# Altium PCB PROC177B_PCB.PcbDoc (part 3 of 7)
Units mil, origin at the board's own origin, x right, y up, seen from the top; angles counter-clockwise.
Board outline 4257.98 x 1561.15 mil, 4 copper layers (Top Layer, Int1 (GND), Int2 (PWR), Bottom Layer), stack 63.572 mil thick; 461 components, 307 nets, 1564 pads, 607 vias.
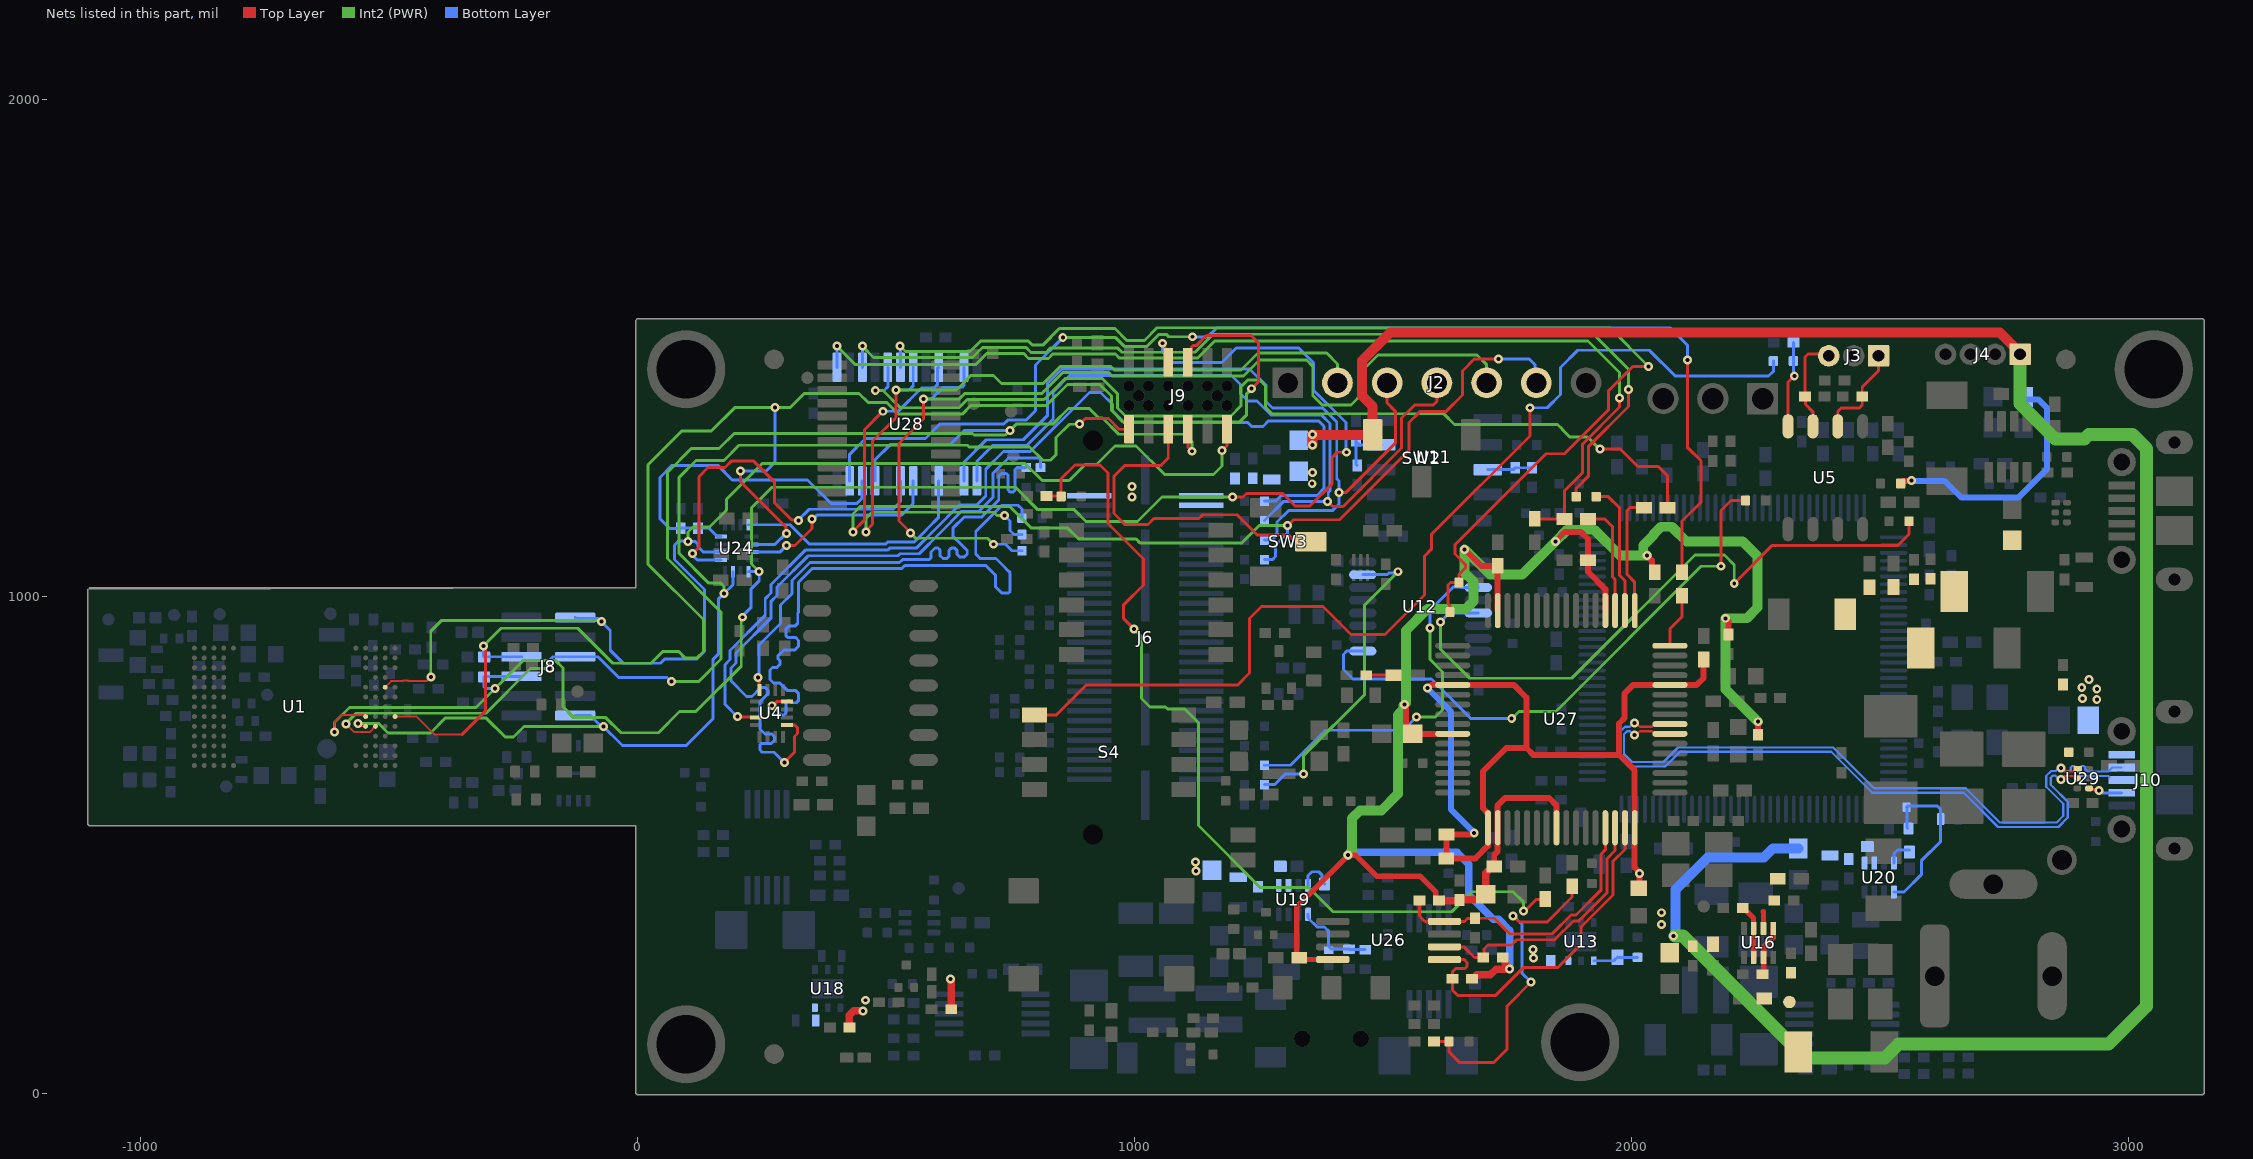
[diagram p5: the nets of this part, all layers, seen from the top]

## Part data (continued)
S3: library part CMP-0002325-1, "Switch, SPST-NO, Off-Mom, 0.01 A, 32 VDC, SMD", CurrentRating_mA=10A, Manufacturer="C&K Components", Supplier Part Number 1=401-1432-2-ND
S4: library part CMP-0002128-3, "Switch, Slide, SPST 4 poles, SMT", CurrentRating_mA=25A, Manufacturer="CTS Electrocomponents", Supplier Part Number 1=CT2184LPST-ND
S5: library part CMP-0002230-1, "Switch, SPST, 2 Pos, 25mA, 24VDC, SMD", CurrentRating_mA=25A, Manufacturer="CTS Electrocomponents", Supplier Part Number 1=CT2182LPST-ND
SW1: library part CMP-0096333-1, "Slide Switch SPDT Surface Mount, Right Angle", Coil Resistance_ohm=80mΩ, Contact Current Rating=100mA, Digikey Part Number=401-2012-1-ND, Manufacturer="C&K Switches", Mouser Part Number=611-AYZ0102AGRLC, Operating Temperature Range="-10°C to +60°C"
SW2: library part CMP-0120644-1, "C & K COMPONENTS - - Schiebeschalter, Subminiatur, SPDT, Ein-Ein, Oberflächenmontage, JS Series, 300 mA", Coil Resistance_ohm=70mΩ, Contact Current Rating=0.3A, Digikey Part Number=CKN10721CT-ND, Manufacturer="C&K Components", Mouser Part Number=611-JS102011JCQN, Operating Temperature Range="-40°C to +85°C"
SW3: library part CMP-0120641-1, "Slide Switch SPDT Surface Mount", Coil Resistance_ohm=100mΩ, Contact Current Rating=100mA, Digikey Part Number=CJS-1200A1-ND, Manufacturer="Nidec Components Corporation", Mouser Part Number=229-CJS-1200A1, Operating Temperature Range="-40°C to +85°C"
TP1 TP2 TP3 TP4 TP5 TP6 TP7 TP8 TP9 TP11 TP12 TP13 TP14 TP15 TP16: library part CMP-0078143-3, "TEST POINT.  No entry in BOM.", Manufacturer=N/A
TP10: library part CMP-0003825-1, "1mm Test Point, SMT", Manufacturer=Any
U1: library part CMP-0120794-2, Manufacturer="Texas Instruments", Operating Temperature Range=to
U2: library part CMP-0078466-1, "ULTRA LOW POWER, 16M-BIT [x 1/x 2/x 4] CMOS MXSMIO (SERIAL MULTI I/O) FLASH MEMORY, SON-8", Manufacturer="Macronix International Co., LTD", Supplier Part Number 1=1092-1178-1-ND
U3: library part CMP-0067398-2, "Automotive Grade, 1.4V-Capable +/-0.5degC Temperature Sensor with Alert Function and I2C/SMBus, DRL0006A (SOT-OTHER-6)", Alternate Manufacturer="Texas Instruments"
U4 U24: library part CMP-0067415-1, "10-Ohm Quad SPDT Analog Switch, RSV0016A (UQFN-16)", Alternate Manufacturer="Texas Instruments"
U5: library part CMP-0075992-1, "Automotive Fault Protected CAN Transceiver With Flexible Data-Rate, D0008A (SOIC-8)", Alternate Manufacturer="Texas Instruments", Alternate PartNumber=TCAN1042HGVDRQ1
U6 U7 U8 U25: library part CMP-0098432-1, "Current Sense Amplifier 1 Circuit 10-VSSOP", Digikey Part Number=296-INA228AIDGSTCT-ND, Input Bias Current=0.01uA, Input Offset Voltage=1mV, Manufacturer="Texas Instruments", Max Supply Voltage=5.5V, Min Supply Voltage=2.7V, Mouser Part Number=595-INA228AIDGST, Nominal Supply Current=640uA, Operating Temperature Range="-40°C to +125°C"
U9 U29: library part CMP-0043115-3, "4-Channel ESD Protection Array for High-Speed Data Interfaces, DRY0006A (USON-6)", Breakdown Voltage(Min)(V)=6, IO Capacitance(Typ)(pF)=1.6, IO Leakage Current(nA)=1, Manufacturer="Texas Instruments", Operating Temperature Range="-40 to 85 C", Rating=Catalog
U10 U14: library part CMP-0029468-1, "400 Mbps Enhanced Product Quad LVDS Transmitter with LVTTL Input and Output, 4 Tx and 0 Rx, -55 to +125 degC, 16-pin SOIC (D), Green (RoHS & no Sb/Br)", Manufacturer="Texas Instruments"
U11: library part CMP-0005309-2, "IC, EEPROM, 8KBIT, 400KHZ, 8SOIC", Manufacturer="ON Semiconductor", Supplier Part Number 1=CAT24C08WI-GT3CT-ND
U12: library part CMP-0067412-1, "0.45-Ohm Quad SPDT Analog Switch Quad-Channel 2:1 Multiplexer/Demultiplexer with Two Controls, PW0016A (TSSOP-16)", Alternate Manufacturer="Texas Instruments"
U13 U18: library part CMP-0013427-7, "500mA LDO, DRV0006A (WSON-6)", Alternate Manufacturer="Texas Instruments"
U15 U28: library part CMP-0092155-1, "3.3-V, 2:1 (SPDT), 6-channel analog multiplexer with 1.8-V compatible control inputs 24-TSSOP -40 to 85", Digikey Part Number=296-24570-1-ND, Manufacturer="Texas Instruments", Max Supply Voltage=3.6V, Min Supply Voltage=1.65V, Mouser Part Number=595-TS3A27518EPWR, Nominal Supply Current=0.01-0.04uA, Octopart Part Number=cf0206a9c1b910c5, On State Resistance=4.4Ω, Operating Temperature Range="-40°C to +85°C"
U16: library part CMP-0088593-2, "1.6 V to 5 V, 2.5-A Low IQ Power Mux With Manual and Automatic Switchover", Manufacturer="Texas Instruments", Max Supply Voltage=5.5V, Min Supply Voltage=1.6V, Nominal Supply Current=0.5-1uA, Operating Temperature Range=to, Output Voltage=0-5.5V
U17: library part CMP-0051215-4, "Single 3-Input Positive-AND Gate, DSF0006A, LARGE T&R", F @ Nom Voltage(Max)(Mhz)=150, Generic Part Number=SN74LVC1G11, ICC @ Nom Voltage(Max)(mA)=0.01, Manufacturer="Texas Instruments", Operating Temperature Range(C)="-40 to 125,-40 to 85", Rating=Catalog, tpd @ Nom Voltage(Max)(ns)=20,7.8,6.2,4.6, Voltage(Nom)(V)=1.8,2.5,3.3,5
U19: library part CMP-0120067-1, "2.7-V to 6-V, 2-A Step-Down Converter in SOT583 Package", Manufacturer="Texas Instruments", Max Supply Voltage=6V, Min Supply Voltage=2.7V, Nominal Supply Current=17uA, Operating Temperature Range="-40°C to +150°C", Output Voltage=0.6-5.5V, Switching Frequency=1.8-4MHz
U20: library part CMP-0120069-1, "2.7-V to 6-V, 2-A Step-Down Converter in SOT583 Package", Manufacturer="Texas Instruments", Max Supply Voltage=6V, Min Supply Voltage=2.7V, Nominal Supply Current=17uA, Operating Temperature Range="-40°C to +150°C", Output Voltage=0.6-5.5V, Switching Frequency=1.8-4MHz
U21: library part CMP-0029856-2, "Tiva C Series Microcontroller, 1024 KB Flash, 256 KB SRAM, 12 Bit, 20 Channels, -40 to 105 degC, 128-Pin TQFP (PDT), Green (RoHS & no Sb/Br), Tray", Manufacturer="Texas Instruments", Temperature Range="-40 to 105 degC"
U22: library part CMP-0033001-1, "Precision Micropower Shunt Voltage Reference, 0.5% accuracy, 2.5 V, 15 ppm / degC, 15 mA, -40 to 125 degC, 3-pin SOT-23 (DBZ), Green (RoHS & no Sb/Br)", Manufacturer="Texas Instruments", Rating=Catalog, Temp Coeff(Max)(ppm/ degree C)=100, Temp Coeff(Typ)(ppm/ degree C)=15
U23: library part CMP-0090433-1, "Local Interconnect Network (LIN) Transceiver with Dominant State Timeout", Manufacturer="Texas Instruments", Max Supply Voltage=36V, Min Supply Voltage=4.5V, Nominal Supply Current=0.3-1.2mA, Operating Temperature Range="-40°C to +150°C"
U26: library part CMP-0081524-1, "1K Microwire Compatible Serial EEPROM, TSSOP-8", Manufacturer=Microchip, Supplier Part Number 1=93LC46B-I/ST-ND
U27: library part CMP-0004747-1, "Quad High Speed USB to Multipurpose UART/MPSSE IC", Manufacturer=FTDI, Supplier Part Number 1=768-1026-1-ND
Y1: library part CMP-0120019-1, "Crystal Resonator 40MHz ±10ppm (Tol) ±20ppm (Stability) 8pF 50Ohm 4-Pin SMD T/R", Frequency Stability=20ppm, Frequency Tolerance=10ppm, Frequency_Fixed=40MHz, Load Capacitance=8pF, Manufacturer=Murata, Operating Temperature Range="-40°C to +105°C"
Y2: library part CMP-0095014-1, "16 MHz ±15ppm Crystal 8pF 80 Ohms 4-SMD, No Lead", Digikey Part Number=50-ECS-160-8-33Q-RES-CT-ND, Frequency_Fixed=16MHz, Frequency Stability=50ppm, Frequency Tolerance=15ppm, Load Capacitance=8pF, Manufacturer=ECS, Mouser Part Number=520-ECS160833QRES-TR, Operating Temperature Range="-40°C to +125°C"
Y3: library part CMP-0081529-1, "Crystal, 12 MHz, 15 ppm, 8 pF, AEC-Q200 Grade 1, SMD", Frequency Stability="50 ppm", Frequency Tolerance="15 ppm", Frequency_Fixed=12MHz, Load Capacitance="8 pF", Manufacturer=NDK, Supplier Part Number 1=644-1128-1-ND
ZZ1: library part CMP-0003616-3
ZZ2: library part CMP-0077236-1
ZZ3: library part CMP-0077237-1
ZZ4 ZZ5: library part CMP-0077238-1

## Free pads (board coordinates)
  round 157.48 hole 118.11: TH1(98.41,1456.71) TH2(1896.85,102.75) TH4(3051.18,1456.69) TH9(98.43,98.43)

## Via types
v1: diameter 18, hole 8, Top Layer to Bottom Layer, tented both sides, 603 vias
v2: diameter 19.68, hole 7.87, Top Layer to Bottom Layer, 4 vias

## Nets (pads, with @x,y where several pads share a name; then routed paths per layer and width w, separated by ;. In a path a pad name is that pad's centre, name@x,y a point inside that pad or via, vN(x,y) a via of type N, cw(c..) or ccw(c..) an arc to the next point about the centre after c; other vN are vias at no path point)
1V2_FB: C100.2 R119.1 R121.2 U19.5 | length 166.4
  Bottom Layer w5.9: U19.5@1349.73,360.08 1349.73,352.79 1368.04,334.48 1382.68,334.48 1391.2,325.97 1391.2,295.69 1397.02,289.86 R119.1@1432.18,289.86 1432.68,289.36 1464.11,289.36 R121.2@1464.61,288.86
1V8_FB: C1.2 R35.2 R36.2 U20.5 | length 333.5
  Bottom Layer w5.9: U20.5@2528.12,404.76 2548.33,404.76 2583.36,439.79 2583.36,467.62 2622.28,506.54 R36.2@2622.28,551.6 2622.28,571.19 2615.58,577.89 2556.03,577.89 C1.2@2553.75,575.6 2554.73,574.62 2554.73,533.43 R35.2@2555.71,532.44
3V3_LDO_EN: R11.2 R241.2 U13.4 | length 91.2
  Bottom Layer w5.9: U13.4@1924.39,266.53 1964.49,266.53 R11.2@1971.93,273.97 1972.44,273.45 R241.2@2012.34,273.45
5V_IN: C42.1 C51.1 C62.1 C66.1 C67.1 C69.2 C72.1 C73.1 C74.1 C134.1 C135.1 J4.1 R30.1 R31.1 R69.2 R76.2 R141.2 R174.2 R238.1 R244.1 SW2.3 U13.6 U16.2 U16.7 U18.6 U19.1 U19.2 U20.1 U20.2 | length 5400.5
  Top Layer w11: R76.2@2224.29,372.62 2226.26,372.62 2230.61,368.27 2230.61,367.69 2245.75,352.54 2245.75,332.14 U16.7@2246.16,331.74 2245.75,331.33 2245.75,305.06 2242.48,301.8 2246.16,298.12 U16.2@2246.16,273.47
  Top Layer w12: R69.2@2541.66,1226.67 2541.66,1227.01 2546.01,1231.36 2562.48,1231.36 v1(2564.01,1232.89)
  Top Layer w15: R174.2@427.08,132.35 427.08,156.98 435.87,165.77 v1(454.21,165.77) ; v1(630,229.6) 630,228.79 631.69,227.1 R141.2@631.69,169
  Top Layer w20: v1(1358.35,1325.28) v1@1358.69,1324.94 ; v1(1358.69,1303.81) v1@1358.69,1324.94 ; J4.1@2782.04,1486.59 2770.39,1498.24 2770.39,1501.49 2741.79,1530.1 1514.28,1530.1 1458.54,1474.35 1458.54,1402.93 1479.68,1381.78 SW2.3@1479.68,1324.48 1359.16,1324.48 v1@1358.69,1324.94
  Int2 (PWR) w26: v1@2088.18,316.08 2104.18,316.08 2348.93,71.33 2510.13,71.33 2537.73,98.93 2960.23,98.93 3036,174.7 3036,1297.46 3008.46,1325 2920.14,1325 2911.5,1316.36 2853.03,1316.36 2782.04,1387.35 J4.1@2782.04,1486.59
  Bottom Layer w12: v1(2564.01,1232.89) 2564.79,1232.11 2630.08,1232.11 2664.07,1198.12 2778.43,1198.12 2836,1255.7 2836,1378.79 2818.74,1396.05 2793.71,1396.05 R31.1@2789.07,1400.7
  Bottom Layer w20: v1(2084.62,316.08) 2088.75,320.22 2088.75,409.49 2153.63,474.37 2266.46,474.37 2284.58,492.48 C72.1@2335.86,492.48
  other v1: 459.51,187.12 1802.86,271.75 1802,289.6 2060.38,339.86 2060.98,363.18 1123.96,447.52 1123.13,465.5
5V_IN_USB: C46.2 C47.1 C50.2 C55.1 C84.1 C85.2 C137.1 D1.1 D12.1 R1.2 U16.6 | length 33.7
  Top Layer w11: 2265.49,365.33 2265.84,364.98 U16.6@2265.84,331.74
5V_REG: C49.1 C136.1 D2.1 R102.2 TP12.1 U16.3 U16.5 | length 101.1
  Top Layer w11: C136.1@2263.68,239.6 2266.01,241.93 U16.3@2266.01,273.3 ; U16.3@2265.84,273.47 2266.25,273.87 2266.25,293.84 2285.19,312.78 2285.19,331.4 U16.5@2285.53,331.74
CAN_PHY_RX: R80.1 U12.5 | length 1320.2
  Top Layer w5.9: v1(2207,1025.6) 2283.67,1102.27 2536.24,1102.27 2558.76,1124.79 R80.1@2558.76,1150.59
  Int2 (PWR) w5.9: v1(1615.79,948.25) 1615.79,893.97 1674.87,834.89 1880.28,834.89 2128,1082.6 2187.17,1082.6 2207,1062.78 v1(2207,1025.6)
  Bottom Layer w5.9: v1(1615.79,948.25) 1633.82,966.28 U12.5@1691.95,966.28
CAN_PHY_TX: R78.1 U12.9 | length 1169.2
  Top Layer w5.9: v1(2180.26,1060.19) 2180.26,1172.34 2200.43,1192.52 R78.1@2229.76,1192.52
  Int2 (PWR) w5.9: v1(1759.37,753.6) 1774.01,768.24 1848.35,768.24 2140.3,1060.19 v1(2180.26,1060.19)
  Bottom Layer w5.9: U12.9@1459.67,889.51 1427.54,889.51 1420.77,882.73 1420.77,852.77 1440.32,833.21 1598.07,833.21 1677.68,753.6 v1(1759.37,753.6)
CAN_STB: R3.2 R71.2 U5.8 | length 174.8
  Top Layer w5.9: U5.8@2315.27,1341.57 2315.27,1430.38 2327.74,1442.84 v1(2327.74,1443.37)
  Bottom Layer w5.9: R71.2@2325.96,1510.51 2325.96,1472.96 2325.96,1445.15 v1(2327.74,1443.37)
CAN_STB_CTRL: R3.1 S4.1 | length 2075.5
  Top Layer w5.9: S4.1@799.68,761.36 843.47,761.36 903.81,821.71 1208.52,821.71 1232,845.19 1232,907.65 1231.96,907.68 1231.96,943.81 1232,943.85 1232,955.29 1256.19,979.48 1379.83,979.48 1436.17,923.15 1504.64,923.15 1583.63,1002.13 1583.63,1080.33 1597.59,1094.28 1597.59,1123.94 1796.09,1322.45 v1(1796.09,1379.06)
  Bottom Layer w5.9: v1(1796.09,1379.06) 1830.83,1379.06 1857.58,1405.81 1857.58,1460.29 1892.04,1494.75 2036.18,1494.75 2088.26,1442.67 2276.17,1442.67 2285.61,1452.11 R3.1@2285.61,1472.96
CANH: J3.3 R68.2 U5.7 | length 198.1
  Top Layer w5.9: U5.7@2365.27,1341.57 2365.06,1341.79 2365.06,1371.18 2350.11,1386.13 2350.11,1400.45 R68.2@2349.1,1401.45 2349.1,1480.88 2355.27,1487.05 2393.75,1487.05 J3.3@2397.23,1483.56
CANL: J3.1 R79.1 U5.6 | length 197.2
  Top Layer w5.9: U5.6@2415.27,1341.57 2415.27,1371.53 2421.9,1378.16 2458.13,1378.16 2464.56,1384.59 R79.1@2464.56,1401.45 2464.56,1420.96 2497.23,1453.63 J3.1@2497.23,1483.56
COMP2: R178.2 U19.4 | length 73.6
  Bottom Layer w5.9: U19.4@1349.73,418.35 1349.73,438.04 1357.37,445.68 1370.99,445.68 1377.28,439.39 1377.28,427.1 R178.2@1383.11,421.26
COMP3: R180.2 U20.4 | length 53.2
  Bottom Layer w5.9: U20.4@2528.12,463.02 2528.12,481.76 2535.64,489.29 R180.2@2559.5,489.29
CONN_5V: C92.1 C93.1 C96.2 J6.1 J6.2 J6.3 R30.2
  other v1: 995.35,1199.21 995.04,1220.86 1358.05,1226.22 1359.02,1249.06
CONN_SOP0_TDO: J9.5 SW3.2 | length 693.2
  Top Layer w5.9: J9.5@1068.36,1335.77 1068.36,1278.08 1053.29,1263 980.67,1263 959.15,1241.48 959.15,1166.05 980.88,1144.32 1027.74,1144.32 1039.42,1156 1130.12,1156 1137.93,1163.8 1206.89,1163.8 1247.91,1122.78 1310.83,1122.78 1318.3,1115.31 1349.14,1115.31 SW3.2@1355.19,1109.26
DCA_FTDI_HOST_INTR_1: R23.2 R152.1 U24.12 U28.10 | length 708.7
  Bottom Layer w5.9: U24.12@168.91,1120.04 161.03,1120.04 144.32,1136.76 R23.2@122.49,1136.76 88.17,1136.76 R152.1@87.87,1136.46 65.14,1136.46 46,1155.6 46,1238.95 70.25,1263.2 162.21,1263.2 191.48,1233.93 342.87,1233.93 389.97,1186.82 442,1186.82 452.27,1197.1 452.27,1231.21 U28.10@453.08,1232.02
DCA_FTDI_SPI_CLK: U24.16 U28.4 | length 494.3
  Bottom Layer w5.9: U24.16@224.02,1143.67 307.63,1143.67 346.12,1105.18 500.11,1105.18 504.07,1109.14 557.48,1109.14 582.05,1133.71 582.05,1134.11 606.62,1158.68 U28.4@606.62,1232.02
DCA_FTDI_SPI_CS: U24.3 U28.6 | length 420.8
  Top Layer w5.9: v1(300.48,1101.72) 317.29,1101.72 351.95,1136.39 v1(351.95,1155.37)
  Bottom Layer w5.9: U24.3@231.9,1088.55 287.04,1088.55 300.22,1101.72 v1(300.48,1101.72) ; v1(351.95,1155.37) 353.81,1155.37 361.46,1163.02 531.99,1163.02 555.12,1186.15 555.12,1231.69 U28.6@555.44,1232.02
DCA_FTDI_SPI_MISO: U24.9 U28.7 | length 775.4
  Top Layer w5.9: v1(111.26,1085.51) 124.23,1098.49 124.23,1240.14 142.7,1258.6 176.73,1258.6 190.49,1272.36 233.53,1272.36 276.67,1229.23 276.67,1187.51 311.2,1152.98 323.7,1152.98 v1(324.17,1152.51)
  Bottom Layer w5.9: v1(111.26,1085.51) 111.26,1082.37 121.01,1072.62 168.72,1072.62 U24.9@168.91,1072.8 ; v1(324.17,1152.51) 324.17,1152.98 346.12,1174.92 514.2,1174.92 529.85,1190.57 U28.7@529.85,1232.02
DCA_FTDI_SPI_MOSI: J8.8 J9.7 U1.E3 U28.9 | length 2894.8
  Top Layer w4: v1(-586.13,743.28) -569.38,726.54 -538.16,726.54 U1.E3@-526.56,738.15
  Top Layer w5.9: J9.7@1107.73,1335.77 1107.73,1300.58 1115.93,1292.38 v1(1115.93,1291.54)
  Int2 (PWR) w5.9: v1(-586.13,743.28) -564.88,764.53 -304.2,764.53 -214.46,854.27 v1(-177,854.27) ; v1(69.31,827.96) 123.16,827.96 168.88,873.69 168.88,967.69 60.76,1075.81 60.76,1249.04 108.67,1296.95 164.59,1296.95 195.13,1327.49 674.34,1327.49 677.7,1324.14 740.31,1324.14 v1@749.28,1333.11 ; v1(749.81,1333.11) 762.65,1345.95 836.15,1345.95 867.72,1377.52 909.49,1377.52 928.6,1358.41 936.08,1358.41 968.69,1325.8 1101.54,1325.8 1115.93,1311.41 v1(1115.93,1291.54)
  Bottom Layer w5.9: v1(-177,854.27) -177,870.35 -169.21,878.14 J8.8@-124.58,878.14 -78.58,878.14 -37.05,836.6 59.8,836.6 68.44,827.96 v1(69.31,827.96) ; U28.9@478.67,1232.02 478.67,1274.27 509.95,1305.55 630.31,1305.55 657.88,1333.11 v1(749.81,1333.11)
DCA_HOST_INTR_1: J2.2 R42.2 U28.19 | length 1747.9
  Top Layer w5.9: v1(460,1129.07) 460,1131.11 473.69,1144.8 473.69,1311.95 521.01,1359.28 v1(521.01,1415.01)
  Int2 (PWR) w5.9: v1(460,1129.07) 460,1156.52 472.32,1168.84 717.37,1168.84 723.67,1162.54 739.02,1162.54 v1(739.06,1162.5) ; v1(521.01,1415.01) 642.25,1415.01 670.96,1443.72 717.02,1443.72 733.09,1427.66 816.89,1427.66 851.13,1461.9 953.44,1461.9 960.34,1455.01 1214.94,1455.01 1249.15,1489.22 1387.14,1489.22 1409.04,1467.33 J2.2@1409.04,1429
  Bottom Layer w5.9: v1(521.01,1415.01) 547.02,1415.01 555.44,1423.43 U28.19@555.44,1460.36 ; v1(739.06,1162.5) 750.24,1151.32 750.24,1131.92 758.23,1123.93 R42.2@774.11,1123.93
DCA_HOST_INTR_GPIO_0_LED: J8.12 J9.11 U1.J2 U24.10 | length 2539.8
  Top Layer w4: U1.J2@-506.87,816.89 -494.86,828.9 -471.78,828.9 -470.67,830.01 -461.28,830.01 -460.28,829.01 -423.78,829.01 -415.51,837.27 v1(-415.12,837.27)
  Top Layer w5.9: v1(1176.44,1292.66) 1176.44,1292.81 1186.47,1302.84 J9.11@1186.47,1335.77
  Int2 (PWR) w5.9: v1(-415.12,837.27) -415.22,837.38 -415.22,929.49 -393.25,951.46 -81.19,951.46 -80.7,950.97 -74,950.97 v1(-71.68,948.66) ; v1(102.51,1110.43) 102.51,1129.32 112.21,1139.02 145.67,1139.02 179.58,1172.94 179.58,1194.87 251.7,1266.99 780.43,1266.99 814.97,1232.44 869.07,1232.44 901.28,1264.65 923.98,1264.65 961.33,1302 1003.79,1302 1061.23,1244.55 1159.24,1244.55 1176.44,1261.75 v1(1176.44,1292.66)
  Bottom Layer w5.9: J8.12@-124.58,956.88 -122.56,954.85 -79.28,954.85 -73.09,948.66 v1(-71.68,948.66) -54.12,931.1 -54.12,891.33 -27.91,865.12 46.89,865.12 55.29,873.53 119.83,873.53 135.27,888.97 135.27,1013.64 75.39,1073.53 75.39,1102.36 83.72,1110.69 v1@102.25,1110.69 ; v1(102.51,1110.43) 116.54,1110.43 122.51,1104.47 122.51,1099.65 133.61,1088.55 U24.10@168.91,1088.55
DCA_RS232_RX: R61.1 U12.3 | length 732.2
  Int2 (PWR) w5.9: v1(1567.97,756.74) 1606.25,756.74 1620.26,770.75 1620.26,847.75 1595.24,872.77 v1(1595.24,935.84)
  Bottom Layer w5.9: R61.1@1262.19,659.92 1314.3,659.92 1384.61,730.23 1541.46,730.23 v1(1567.97,756.74) ; v1(1595.24,935.84) 1595.24,972.22 1641.59,1018.57 1656.74,1018.57 1657.85,1017.46 U12.3@1691.95,1017.46
DCA_RS232_TX: R62.1 U12.15 | length 646.3
  Int2 (PWR) w5.9: v1(1340.89,642.19) 1340.89,679.79 1463.53,802.42 1463.53,982.29 v1(1530.41,1049.17)
  Bottom Layer w5.9: R62.1@1262.19,620.73 1282.16,620.73 1303.62,642.19 v1(1340.89,642.19) ; U12.15@1459.67,1043.05 1460.33,1043.71 1509.26,1043.71 1512.56,1047.01 1528.25,1047.01 v1(1530.41,1049.17)
DCA_SPI_CLK: J2.3 R41.1 U28.2 | length 1611.5
  Top Layer w5.9: v1(1411.67,1208.61) 1412.12,1208.16 1425.56,1208.16 1525.21,1307.81 1525.21,1372.04 1508.83,1388.42 J2.3@1508.83,1429.21
  Bottom Layer w5.9: U28.2@657.8,1232.02 657.8,1269.97 702.48,1314.65 776.9,1314.65 825.1,1362.84 825.1,1428.05 854.21,1457.16 1232.02,1457.16 1264.81,1424.37 1264.81,1391.81 1278.03,1378.6 1379.21,1378.6 1407.37,1350.44 1407.37,1236.25 1411.67,1231.95 v1(1411.67,1208.61) 1411.67,1185.14 1398.49,1171.96 1310.23,1171.96 1287.29,1149.02 1287.29,1123.06 1276.94,1112.7 R41.1@1262.19,1112.68
DCA_SPI_CLK_I2C_SCL: J8.7 J9.8 R75.1 U1.F1 U24.2 | length 3501.1
  Top Layer w4: U1.F1@-487.19,757.83 -443.74,757.83 -407.96,722.05 -351.88,722.05
  Top Layer w5.9: -351.88,722.05 -305.4,768.53 -305.4,893.16 -309.12,896.88 v1(-309.12,899.58) ; v1(208.26,1251.88) 208.26,1229.96 299.55,1138.67 299.55,1126.2 v1(300.04,1125.72) ; J9.8@1107.73,1470.81 1114.62,1477.7 1114.62,1500.5 1118.08,1503.96 1124.91,1503.96 1145.25,1524.3 1235.22,1524.3 1249.58,1509.93 1249.58,1431.1 1236.3,1417.82 v1(1236.3,1417.33)
  Int2 (PWR) w5.9: v1(-309.12,899.58) -309.12,900.35 -273.97,935.49 -119.34,935.49 -48.97,865.12 27.95,865.12 51.95,889.12 83.14,889.12 96.97,875.28 119.99,875.28 133.18,888.47 133.18,952.84 21.86,1064.16 21.86,1264.32 90.19,1332.65 149.8,1332.65 196.36,1379.2 v1(277,1379.2) 307.25,1379.2 336.05,1408 446.29,1408 464.37,1389.92 501.67,1389.92 525.52,1366.08 653.79,1366.08 671.74,1384.02 823.74,1384.02 865.69,1425.98 930.72,1425.98 954.26,1402.44 954.26,1373.89 978.09,1350.06 1211.38,1350.06 1226.23,1364.92 1226.23,1407.23 v1@1236.3,1417.3
  Bottom Layer w5.9: v1(-309.12,899.58) -309.12,879.22 R75.1@-307.64,877.74 -307.24,878.14 J8.7@-232.85,878.14 ; v1(208.26,1251.88) 259.49,1251.88 277,1269.38 v1(277,1379.2) ; U24.2@231.9,1104.3 277.48,1104.3 298.9,1125.72 v1(300.04,1125.72)
DCA_SPI_CS: J2.4 R39.1 U28.1 | length 1589.8
  Top Layer w5.9: v1(1388.89,1190.89) 1399.36,1180.41 1420.36,1180.41 1537.79,1297.84 1537.79,1358.17 1564.63,1385 1601.72,1385 1609,1392.28 1609,1429.04 J2.4@1608.83,1429.21
  Bottom Layer w5.9: U28.1@683.39,1232.02 683.39,1271.54 714.58,1302.73 783.42,1302.73 837,1356.31 837,1411.07 869.71,1443.78 1195.8,1443.78 1213.94,1425.65 1213.94,1407.41 1228.58,1392.77 1247.03,1392.77 1274.99,1364.8 1376.17,1364.8 1393.52,1347.46 1393.52,1212.01 1390.25,1208.74 1390.25,1192.25 v1(1388.89,1190.89) 1300.71,1190.89 1262.19,1152.37 R39.1@1262.19,1151.87
DCA_SPI_CS_I2C_SDA: J8.5 J9.6 R4.1 U1.F4 U24.5 | length 3575.3
  Top Layer w4: v1(-608.65,726.98) -608.65,746.94 -594.59,760.99 -549.4,760.99 U1.F4@-546.24,757.83
  Top Layer w5.9: v1(1057.01,1508.83) 1057.01,1505.56 1061.47,1501.1 1061.47,1477.7 J9.6@1068.36,1470.81 ; v1(1197.32,1199.53) 1218.96,1199.53 1225.77,1206.33 1298.75,1206.33 1323.74,1181.34 1353.12,1181.34 1398.15,1226.38 1398.15,1279.15 1408.53,1289.53 v1(1426.53,1289.53)
  Int2 (PWR) w5.9: v1(-608.65,726.98) -608.65,746.22 -578.78,776.08 -323.93,776.08 -229.8,870.22 -163.91,870.22 -149.23,855.54 -149.23,819.89 -149.23,777.53 -127.35,755.64 -63,755.64 -32.59,725.23 42.83,725.23 85.41,767.82 118.01,767.82 209.38,859.18 209.38,955.42 v1(211.58,957.63) ; v1(245.55,1049.24) 229.85,1064.93 229.85,1177.82 271.13,1219.1 760.99,1219.1 806.03,1174.07 879.38,1174.07 902.97,1150.47 1006.59,1150.47 1055.64,1199.53 v1(1197.32,1199.53)
  Bottom Layer w5.9: v1(-285.67,814.35) -304.39,814.35 -307.84,817.8 R4.1@-307.84,837.53 -306.61,838.77 J8.5@-232.85,838.77 ; v1(211.58,957.63) 211.58,959.57 228.68,976.66 228.68,1014.01 245.55,1030.88 v1(245.55,1049.24) 224.08,1049.24 U24.5@224.02,1049.18 ; v1(1057.01,1508.83) 1057.01,1491.54 1078.3,1470.25 1176.41,1470.25 1205.31,1499.15 1331.04,1499.15 1360.78,1469.41 1360.78,1414.27 1425.93,1349.11 1425.93,1290.13 v1(1426.53,1289.53)
DCA_SPI_MISO: J2.5 R53.2 U28.23 | length 2024.6
  Top Layer w5.9: v1(550.05,1127.09) 550.05,1127.95 526.5,1151.5 526.5,1306.88 575.97,1356.34 v1(575.97,1397.06)
  Int2 (PWR) w5.9: v1(550.05,1127.09) 560.59,1116.55 705,1116.55 v1(717.07,1104.49) ; v1(575.97,1397.06) 648.13,1397.06 658.89,1407.82 813.88,1407.82 856.06,1450 948.51,1450 955.41,1443.11 1219.87,1443.11 1252.07,1475.32 1346.35,1475.32 1359.04,1462.63 1359.04,1403.88 1378.16,1384.76 1435.98,1384.76 1460.42,1409.2 1460.42,1455.24 1490.38,1485.19 1689.28,1485.19 1709.04,1465.43 J2.5@1709.04,1429
  Bottom Layer w5.9: v1(575.97,1397.06) 592.29,1397.06 615.57,1420.34 653.89,1420.34 657.35,1423.8 657.35,1459.91 U28.23@657.8,1460.36 ; v1(717.07,1104.49) 741.11,1104.49 754.23,1091.37 R53.2@774.17,1091.37
DCA_SPI_MISO_REG_MODE: J8.2 J9.1 U1.E4 U24.7 | length 2487.1
  Top Layer w4: v1(-561.79,743.54) -558,743.54 -553.66,739.2 -547.29,739.2 U1.E4@-546.24,738.15
  Top Layer w5.9: v1(890.14,1345.93) 901.52,1357.3 947.98,1357.3 969.52,1335.77 J9.1@989.62,1335.77
  Int2 (PWR) w5.9: v1(-561.79,743.54) -519.54,743.54 -500.99,724.99 -415.95,724.99 -386.3,754.63 -303.37,754.63 -265.44,716.7 -248.98,716.7 -227.88,737.81 v1(-67.72,737.81) ; v1(174.75,1005.19) 174.75,1019.52 168.16,1026.11 144.12,1026.11 84.56,1085.67 84.56,1239.18 118.53,1273.15 174.45,1273.15 204.99,1303.69 664.48,1303.69 667.84,1300.34 789.36,1300.34 816.27,1273.43 831.74,1273.43 842.66,1284.36 842.66,1284.76 842.8,1284.9 842.8,1318.94 869.78,1345.93 v1(890.14,1345.93)
  Bottom Layer w5.9: J8.2@-124.58,760.03 -94.07,760.03 -74.17,740.12 -70.04,740.12 -29.32,699.4 98.82,699.4 152.18,752.77 152.18,872.13 163.21,883.15 163.21,993.82 v1@174.58,1005.19 ; v1(174.75,1005.19) v1@174.58,1005.19 ; U24.7@192.53,1049.18 192.53,1023.14 v1@174.58,1005.19
DCA_SPI_MOSI: J2.6 R52.1 U28.21 | length 2233.8
  Top Layer w5.9: v1(433.95,1129.07) 433.95,1129.94 457.76,1153.75 457.76,1335.5 v1(494.23,1371.97) ; v1(1308.36,1141.75) 1320.32,1153.71 1412.92,1153.71 1552.65,1293.45 1552.65,1349.46 1574.28,1371.08 1626.72,1371.08 1660.21,1404.58 1660.21,1453.13 1683.96,1476.87 v1(1732.85,1476.87)
  Int2 (PWR) w5.9: v1(433.95,1129.07) 433.95,1165.27 449.42,1180.74 748.87,1180.74 792.05,1137.56 865.39,1137.56 888.18,1114.77 1003.83,1114.77 1011.25,1107.35 1216.76,1107.35 1251.16,1141.75 v1(1308.36,1141.75)
  Bottom Layer w5.9: v1(494.23,1371.97) 525.35,1371.97 571.97,1418.59 596.99,1418.59 603.84,1425.44 603.84,1457.58 U28.21@606.62,1460.36 ; R52.1@1262.19,1073.49 1277.72,1073.49 1284.07,1079.84 1284.07,1103.01 1308.36,1127.3 v1(1308.36,1141.75) ; v1(1732.85,1476.87) 1794.75,1476.87 1806.11,1465.5 1806.11,1431.92 J2.6@1808.83,1429.21
DCA_TCK: R38.2 U4.16 | length 1045.2
  Top Layer w5.9: v1(243.06,836.59) 243.06,833.32 245.44,830.94 245.44,812.19 U4.16@246.23,811.41
  Bottom Layer w5.9: v1(243.06,836.59) 245.28,838.81 245.28,901.6 288.6,944.92 288.6,982.36 311.3,1005.06 311.3,1031.51 347.66,1067.87 528,1067.87 533.57,1073.44 587.09,1073.44 591,1077.36 591,1088.67 599.08,1096.75 605.44,1096.75 608.89,1093.29 608.89,1082.02 615.24,1075.67 623.01,1075.67 627.59,1080.25 627.59,1092.19 632,1096.6 639,1096.6 643,1092.6 643,1084.6 649,1078.6 658,1078.6 664,1084.6 664,1092.15 635.03,1121.12 635.03,1136.47 657.53,1158.96 692.62,1158.96 727.37,1193.71 727.37,1193.78 ; 727.39,1193.8 727.39,1241.69 732.69,1246.99 742.3,1246.99 746.35,1242.94 746.35,1213.48 750.68,1209.16 756.35,1209.16 760.13,1212.94 760.13,1255.1 763.98,1258.94 R38.2@782.6,1258.94
DCA_TDI: R37.1 U4.3 | length 1955.6
  Top Layer w5.9: v1(201.43,758.09) 202.33,757.19 237.45,757.19 U4.3@238.35,756.29
  Bottom Layer w5.9: v1(201.43,758.09) 201.04,758.09 177,782.13 177,862.49 187.01,872.5 187.01,890.84 257.64,961.47 257.64,994.82 269.35,1006.53 269.35,1023.36 339.27,1093.28 505.04,1093.28 509,1097.24 562.41,1097.24 598.07,1132.9 598.07,1133.16 648.13,1183.22 683.08,1183.22 701.22,1201.36 701.22,1255.16 736.89,1290.83 790.92,1290.83 910.05,1409.96 932.24,1409.96 955.98,1386.22 955.98,1373.48 980.41,1349.04 1228.77,1349.04 1236.26,1341.55 1258.95,1341.55 1270.23,1352.83 1370.49,1352.83 1381.62,1341.71 1381.62,1216.94 1367.47,1202.79 1295.78,1202.79 1284.06,1191.07 R37.1@1262.19,1191.07
DCA_TDO: R34.2 U4.9 | length 1341.6
  Top Layer w5.9: v1(296,665.6) 316.35,685.95 316.35,717.46 322.69,723.8 322.69,735.42 317.69,740.42 301.47,740.42 U4.9@301.34,740.54
  Bottom Layer w5.9: v1(296,665.6) 275.51,686.09 251.51,686.09 247.09,690.51 247.09,701.26 249.32,703.48 269.88,703.48 276,709.6 276,717.6 271,722.6 256.9,722.6 247.09,732.41 247.09,787.84 263,803.75 263,810.6 257,816.6 249,816.6 230.8,798.41 220.2,798.41 188.9,829.71 188.9,855.5 198.91,865.51 198.91,885.84 269.59,956.52 269.59,989.87 281.3,1001.58 281.3,1018.41 344.27,1081.38 524.68,1081.38 528.64,1085.34 567.34,1085.34 609.97,1127.97 609.97,1128.23 652.6,1170.86 687.62,1170.86 715.49,1198.72 715.49,1246.62 746.93,1278.06 807.77,1278.06 811.29,1274.55 R34.2@811.29,1258.72
DCA_TMS: R40.2 U4.12 | length 1264.3
  Top Layer w5.9: v1(271.7,779.63) 272.67,779.63 280.74,787.7 301.26,787.7 U4.12@301.34,787.79
  Bottom Layer w5.9: v1(271.7,779.63) 290.42,760.91 295.31,760.91 299,764.6 299,785.8 302.45,789.26 307.34,789.26 311,785.6 320,785.6 325,790.6 325,803.6 318,810.6 302,810.6 287,825.6 274,825.6 267,832.6 267,851.61 271.99,856.6 281,856.6 287,862.6 287,870.6 283,874.6 283,879.6 295.21,891.81 317.21,891.81 324.5,899.1 324.5,911.1 319,916.6 303,916.6 299,920.6 299,933.6 305,939.6 317,939.6 323,945.6 323,965.99 324.5,967.49 324.5,1027.88 352.59,1055.97 532.93,1055.97 538.5,1061.54 701.39,1061.54 720.58,1042.35 720.58,1019.52 733.45,1006.64 747.02,1006.64 750.48,1010.1 750.48,1046.92 742.17,1055.22 742.17,1055.43 722,1075.6 690.08,1075.6 681.09,1084.59 681.09,1129.92 734.16,1182.99 766.28,1182.99 773.98,1175.29 R40.2@773.98,1156.72
EECLK: R167.1 U26.2 U27.62 | length 536.3
  Top Layer w5.9: U26.2@1623.99,294.6 U26.2@1623.99,294.6 1662.85,294.55 1684.23,273.16 R167.1@1702.14,273.16 1703.42,274.44 1703.42,289.96 1711.52,298.06 1758.65,298.06 1769.41,308.82 1845.61,308.82 1883.52,346.74 1894.17,346.74 1951.43,404 1951.43,472.28 1967.38,488.23 U27.62@1967.38,534.06
EECS: R168.1 U26.1 U27.63 | length 703.2
  Top Layer w5.9: U26.1@1623.99,269.01 1663.68,269.01 1669.65,263.05 1669.65,255.7 1665.24,251.29 1646.98,251.29 1640.31,244.62 R168.1@1640.31,230.6 1640.31,207.42 1651.33,196.41 1726.32,196.41 1783.36,253.45 1852.26,253.45 1898.8,299.99 1898.8,334.54 1963.33,399.07 1963.33,466.7 1987.06,490.44 U27.63@1987.06,534.06
EEDATA: R184.1 R185.1 U26.4 U27.61 | length 581.8
  Top Layer w5.9: R184.1@1573.61,387.57 1573.92,387.25 1573.92,356.37 1584.51,345.78 1664.64,345.78 1670.49,351.63 1685.28,351.63 R185.1@1685.72,352.07 1724.22,352.07 1755.57,320.72 1840.68,320.72 1878.59,358.64 1888.88,358.64 1938.53,408.29 1938.53,480.58 1947.69,489.75 U27.61@1947.69,534.06
EEPROM_A2: R161.1 R162.2 U11.3 | length 106
  Bottom Layer w5.9: R161.1@1448.43,1262.85 1446,1265.29 R162.2@1446,1311.37 ; U11.3@1496.57,1304.47 1452.89,1304.47 R162.2@1446,1311.37 ; R162.2@1446,1311.37 R162.2@1446,1312.92 R162.2@1446,1311.37
EEPROM_WPn: R157.1 R158.2 U11.7 | length 90.8
  Bottom Layer w6: U11.7@1711.14,1254.47 1762.45,1254.47 R157.1@1766.32,1258.35 R158.2@1800.31,1258.35
FTDI_3V3: C138.1 C149.2 C150.1 C151.2 C152.1 C153.1 L2.1 L3.1 L7.2 R167.2 R168.2 R184.2 R237.1 U26.8 U27.20 U27.31 U27.42 U27.50 U27.56 | length 4234.8
  Top Layer w11: U26.8@1399.5,269.09 1335.13,269.09 1326.43,277.79 1326.43,375.04 v1@1430,478.6 ; v1(1430,479.6) v1@1430,478.6 ; R184.2@1612.98,387.57 1611.31,387.57 1606.97,391.91 1606.97,404.55 1574.62,436.89 1487.72,436.89 1446.01,478.6 v1@1430,478.6
  Top Layer w12: v1(1543.57,782.05) 1543.57,780.89 1546.92,777.54 1546.92,735.74 1559.62,723.04 U27.42@1640.61,723.04 ; v1(1663.95,1093.96) 1665.21,1093.96 1698.09,1061.07 C152.1@1731.16,1061.07 U27.31@1731.16,971.07 ; C150.1@1724.17,456.06 1724.17,479.88 1731.06,486.77 1731.06,533.97 U27.50@1731.16,534.06 1731.16,579.28 1746.21,594.33 1834.31,594.33 1849.17,579.47 1849.17,534.16 U27.56@1849.27,534.06 ; v1(1847.34,1110.1) 1866.52,1129.28 1898.3,1129.28 1912.68,1114.9 C153.1@1912.68,1072.47 1912.68,1049.04 1947.69,1014.03 U27.20@1947.69,971.07 ; v1(2031.56,1081.6) 2031.56,1081.22 2041.21,1071.57 2041.21,1054.14 R237.1@2047,1048.35 ; v1(2189.56,955.57) 2195.5,949.63 L3.1@2195.5,922.87 ; L2.1@2254.74,721 v1(2254.74,747.42)
  Top Layer w15: R184.2@1612.98,387.57 1652.98,387.57 L7.2@1654.28,388.87 1694.24,388.87 1706.09,400.73 C149.2@1707.08,400.73 1707.08,442.96 1715.86,451.75 1719.86,451.75 C150.1@1724.17,456.06 ; R168.2@1679.68,230.6 1682.03,232.94 1683.99,232.94 1689.12,238.07 1715.94,238.07 1727.71,249.84 1754.37,249.84 v1(1754.94,250.42) 1754.94,251.23 1745.82,260.35 1745.82,270.81 1743.47,273.16 R167.2@1741.51,273.16
  Int2 (PWR) w20: v1(1430,479.6) 1438.33,487.93 1438.33,553.32 1453.88,568.86 1497.31,568.86 1530.9,602.45 1530.9,761.33 1541.26,771.69 1541.26,779.74 v1(1543.57,782.05) 1546.83,785.31 1546.83,931.25 1589.58,974 1666.55,974 1682.39,989.84 1682.39,1029.48 1663.95,1047.92 v1(1663.95,1093.96) ; v1@1667.02,1092.14 1715.87,1043.3 1780.54,1043.3 v1(1847.34,1110.1) 1870.9,1133.66 1925.3,1133.66 1977.35,1081.6 v1@2024,1081.6 ; v1(2031.56,1081.6) v1@2024,1081.6 ; v1(2254.74,747.42) 2189.56,812.61 v1(2189.56,955.57) 2232.54,955.57 2254,977.03 2254,1080.39 2224.14,1110.24 2110.81,1110.24 2081.4,1139.65 2059.61,1139.65 2045.67,1125.71 2045.67,1123.65 2024,1101.98 v1@2024,1081.6
  Bottom Layer w15: v1(1430,479.6) 1430.81,479.6 1435.64,484.43 1649.51,484.43 1673.08,460.86 1673.08,399.4 1722.21,350.28 1732.98,350.28 1754.94,328.32 v1(1754.94,250.42)
FTDI_HOST_INTR_1: R216.2 R217.2 U28.18 | length 2362.1
  Top Layer w5.9: R217.2@1635.14,968.15 1635.14,981.35 1631.23,985.26 1631.23,1022.23 1636.4,1027.4 R216.2@1653.17,1027.4 1653.17,1043.97 1666.06,1056.86 1666.06,1063.87 1645.19,1084.74 1645.19,1103.53 1828.19,1286.53 1865.46,1286.53 1953.9,1374.97 1953.9,1413.26 2002.94,1462.3 v1(2034.73,1462.3)
  Int2 (PWR) w5.9: v1(529,1502.89) 539.79,1492.1 669.79,1492.1 690.66,1512.97 787.22,1512.97 795.25,1504.95 815.74,1504.95 849.26,1538.46 961.03,1538.46 984.98,1514.51 1020.47,1514.51 1045.97,1540 1957.03,1540 v1(2034.73,1462.3)
  Bottom Layer w5.9: v1(529,1502.89) 529.42,1502.47 529.42,1460.79 U28.18@529.85,1460.36
FTDI_MISO: R189.1 U27.18 | length 267.4
  Top Layer w5.9: R189.1@1929.31,1200.19 1953.75,1200.19 1975.74,1178.2 1975.74,1042.4 1987.06,1031.08 U27.18@1987.06,971.07
FTDI_MOSI: R187.1 U27.17 | length 244.3
  Top Layer w5.9: U27.17@2006.75,971.07 2006.75,1028.23 1991.05,1043.93 1991.05,1171.87 1997.33,1178.15 R187.1@2025.4,1178.15
FTDI_SOP0: R13.1 R43.2 R249.2 | length 658.5
  Top Layer w5.9: R13.1@1603.1,104.1 R43.2@1633.1,104.1 1633.1,83.44 1654.94,61.6 1722.61,61.6 1749.68,88.67 1749.68,175.29 v1(1798,223.6) ; v1(1761.58,357.06) 1762.1,357.06 1774.63,344.52 1830.82,344.52 1880.88,394.58 R249.2@1880.88,416.34
  Bottom Layer w5.9: v1(1761.58,357.06) 1762.53,357.06 1780.28,339.31 1780.28,241.32 v1(1798,223.6)
FTDI_SOP1: R16.1 R67.2 R248.2 | length 1855.5
  Top Layer w5.9: R16.1@823.7,1201.3 852.45,1201.3 R67.2@853.05,1200.7 853.05,1236.65 880.56,1264.16 931.07,1264.16 947.25,1247.98 947.25,1146.07 1018.51,1074.8 1018.51,1022.72 978.66,982.87 978.66,954.77 v1(999.83,933.6) ; v1(1783.41,367.03) 1786,367.03 1808.44,389.47 R248.2@1826.69,389.47
  Int2 (PWR) w5.9: v1(999.83,933.6) 1014.55,918.91 1014.55,794.25 1031.46,777.34 1062.73,777.34 1066.63,773.44 1101.18,773.44 1129.16,745.46 1129.16,538.51 1253.67,414 1350.84,414 1399.62,365.21 1638.67,365.21 1678.88,405.42 1762.18,405.42 1783.41,384.19 v1(1783.41,367.03)
FTDI_SPI_CLK: R186.2 U28.11 | length 2414.2
  Top Layer w5.9: R186.2@2102,1048.3 2102,1150.96 2139.9,1188.86 2139.9,1272.29 2112.64,1299.55 v1(2112.64,1475.29)
  Int2 (PWR) w5.9: v1(856.21,1520.02) 962.64,1520.02 980.05,1502.61 1025.4,1502.61 1049.58,1526.78 1064.45,1526.78 1069.32,1521.91 v1(1117.48,1521.91)
  Bottom Layer w5.9: U28.11@427.49,1232.02 427.49,1285.48 459.46,1317.45 579.94,1317.45 608.77,1346.28 737.6,1346.28 745.43,1354.11 782.23,1354.11 801.3,1373.18 801.3,1465.11 v1(856.21,1520.02) ; v1(1117.48,1521.91) 1117.66,1521.73 1147.73,1521.73 1165.2,1539.2 2078.8,1539.2 2112.64,1505.36 v1(2112.64,1475.29)
FTDI_SPI_CS: R99.1 R209.2 U28.13 | length 2093
  Top Layer w5.9: R99.1@1805.44,1155.5 R209.2@1865.44,1155.5 1865.44,1212.05 1902.15,1248.77 1902.15,1306.4 1976.27,1380.51 v1(1976.27,1398.74)
  Int2 (PWR) w5.9: v1(402,1502.89) 438.44,1466.45 681.46,1466.45 703.19,1488.18 777.65,1488.18 787.44,1478.39 827.42,1478.39 835.96,1486.94 962.06,1486.94 970.19,1478.81 1127.3,1478.81 1161.88,1513.39 1912.98,1513.39 1976.27,1450.1 v1(1976.27,1398.74)
  Bottom Layer w5.9: U28.13@401.9,1460.36 401.95,1460.42 401.95,1502.84 v1(402,1502.89)
FTDI_SPI_MISO: R189.2 U28.15 | length 1956.4
  Top Layer w5.9: R189.2@1888.96,1200.19 1888.96,1216.85 1914.22,1242.11 1914.22,1301.63 1994.22,1381.63 v1(1994.22,1415.54)
  Int2 (PWR) w5.9: v1(453,1502.89) 475.69,1480.2 674.72,1480.2 694.6,1500.08 782.58,1500.08 792.37,1490.29 822.49,1490.29 831.03,1498.84 966.99,1498.84 975.12,1490.71 1122.37,1490.71 1158.55,1526.89 1923.79,1526.89 1994.22,1456.46 v1(1994.22,1415.54)
  Bottom Layer w5.9: v1(453,1502.89) v1(453,1502.89) 453.04,1460.4 U28.15@453.08,1460.36
FTDI_SPI_MOSI: R187.2 U28.17 | length 1969.5
  Top Layer w5.9: v1(1936.6,1295.68) 1978.32,1295.68 2013.02,1260.98 2054.04,1260.98 2072.65,1242.38 R187.2@2072.65,1178.15
  Int2 (PWR) w5.9: v1(479,1413.6) 494.82,1413.6 529.31,1379.11 647.35,1379.11 664.16,1395.92 818.81,1395.92 860.76,1437.88 935.65,1437.88 966.16,1407.37 966.16,1378.82 982.24,1362.74 1194.35,1362.74 1214.33,1382.72 1214.33,1420.75 1228.86,1435.28 1252.18,1435.28 1264.12,1423.33 1264.12,1380.27 1277.36,1367.03 1622.66,1367.03 1644.18,1345.51 1851.49,1345.51 1861.35,1335.65 1861.35,1334.77 1875.92,1320.19 1912.1,1320.19 v1(1936.6,1295.68)
  Bottom Layer w5.9: v1@479.17,1413.78 496.58,1413.78 504.26,1421.45 U28.17@504.26,1460.36
FTDI_SPICLK: R186.1 U27.16 | length 110.9
  Top Layer w5.9: U27.16@2077.62,900.21 2077.62,934.29 2102,958.68 R186.1@2102,1001.05
FTDI_SPICS: R209.1 U27.19 | length 226.9
  Top Layer w5.9: R209.1@1912.68,1155.5 1946.58,1155.5 1962.35,1139.72 1962.35,1038.97 1967.38,1033.94 U27.19@1967.38,971.07
FTDI_SUSPEND_N: R251.2 R252.1 | length 55
  Top Layer w5.9: R252.1@1466.57,841.15 R251.2@1521.55,841.15
FTDI_USBD_N: J10.2 U27.7 U29.1 | length 1442.9
  Top Layer w4.5: v1(2006,720.88) 2009.65,720.88 2017.15,728.38 2041.8,728.38 2047.14,723.04 U27.7@2077.62,723.04 ; v1(2864,654.79) 2865.89,654.79 2873.39,647.29 2881.25,647.29 2881.4,647.44 2888.88,647.44 2894.22,652.78 U29.1@2898.1,652.78
  Bottom Layer w4.5: v1(2006,720.88) 2004.08,720.88 1996.61,728.35 1991.06,728.35 1985.18,722.46 1985.18,682.45 2001.14,666.49 2064.69,666.49 2094.01,695.81 2406.04,695.81 2488.3,613.55 2672.65,613.55 2741.32,544.87 2855.56,544.87 2869.07,558.38 2869.07,582.45 2834.88,616.64 2834.88,638.5 2844.67,648.3 2853.86,648.3 2860.35,654.79 v1(2864,654.79) 2865.89,654.79 2873.39,647.29 2881.21,647.29 2883.85,649.92 2883.85,655.54 2886.85,658.55 2890.58,658.55 2893.33,655.8 2893.33,651.39 2897.43,647.29 2900.34,647.29 2902.98,649.92 2902.98,655.54 2905.99,658.55 2909.71,658.55 2912.46,655.8 2912.46,651.39 2916.56,647.29 2959.26,647.29 J10.2@2961.9,649.92 ; J10.2@2961.9,649.96 2967.52,655.58 J10.2@2986.22,655.58
FTDI_USBD_P: J10.3 U27.8 U29.2 | length 1415.5
  Top Layer w4.5: v1(2006,744.88) 2009.65,744.88 2017.15,737.38 2041.8,737.38 2047.14,742.73 U27.8@2077.62,742.73 ; v1(2864,630.79) 2865.89,630.79 2873.39,638.29 2884.97,638.29 2885.12,638.44 2888.88,638.44 2894.22,633.09 U29.2@2897.11,633.09
  Bottom Layer w4.5: v1(2006,744.88) 2004.11,744.88 1996.58,737.35 1987.33,737.35 1976.18,726.19 1976.18,678.72 1997.41,657.49 2068.42,657.49 2097.74,686.81 2402.31,686.81 2484.57,604.55 2668.92,604.55 2737.6,535.87 2859.29,535.87 2878.07,554.65 2878.07,586.17 2875.44,588.81 2848.59,615.66 2843.88,620.37 2843.88,634.77 2848.4,639.3 2852.54,639.3 2861.05,630.79 v1(2864,630.79) 2865.89,630.79 2873.39,638.29 2959.26,638.29 J10.3@2961.9,635.65
FTDI_USBID: J10.4 U29.4 | length 69.2
  Top Layer w5.9: U29.4@2920.73,613.41 2922.67,611.48 2934.76,611.48 2937.21,609.03 v1(2940.48,609.03)
  Bottom Layer w5.9: v1(2940.48,609.03) 2943.76,609.03 2948.39,604.4 J10.4@2986.22,604.4
FTDI_VBUS: C157.1 J10.1 L8.1 R259.2
  other v1: 2936.28,792.3 2907.93,793.93 2936.28,813.4 2906.09,815.85 2920.45,832.52
FTDI_VCORE: C139.1 C140.1 C143.1 C144.1 U27.12 U27.37 U27.49 U27.64 | length 1920.6
  Top Layer w12: v1(1589.73,815.26) 1591.35,815.26 1597.46,821.37 1640.51,821.37 U27.37@1640.61,821.47 1763.51,821.47 1789,795.97 1789,694.6 ; C144.1@1627.87,472.34 C144.1@1627.95,472.42 ; v1(1683.93,523.91) 1682.3,523.91 1679.17,520.77 C143.1@1628.03,520.77 1627.95,520.69 C144.1@1627.95,472.42 ; C139.1@2015.1,412.36 2015.95,413.2 2015.95,441.66 v1(2016.79,442.5) ; v1@2016.26,441.97 2016.26,444.66 2006.75,454.17 2006.75,649.47 1975.29,680.93 ; C140.1@2145.41,872.63 2145.41,835.54 2131.33,821.47 U27.12@2077.62,821.47 2003.53,821.47 1986.56,804.49 1986.56,755.14 1975.29,743.87 1975.29,680.93 ; C144.1@1627.95,472.42 1686.15,472.42 1711.47,497.74 U27.49@1711.47,534.06 1711.47,563.4 1701.53,573.35 1701.53,647.77 1748.37,694.6 1789,694.6 ; 1789,694.6 1802.67,680.93 1975.29,680.93
  Bottom Layer w12: v1(1589.73,815.26) 1637.4,767.59 1637.4,570.44 v1(1683.93,523.91)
